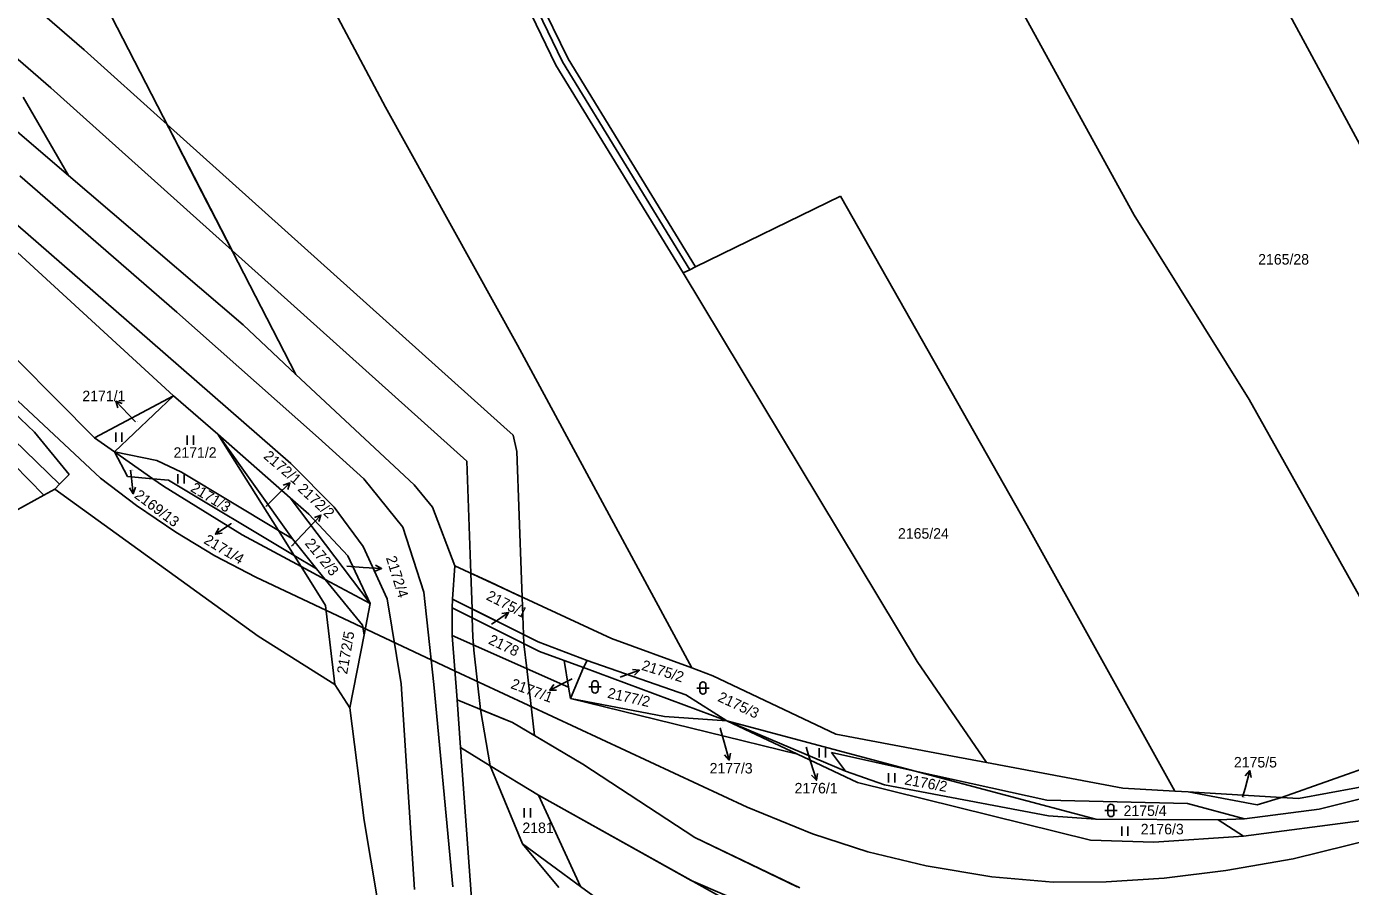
# Model space of a CAD drawing. Extents: x -785744 to -782822, y -1067550 to -1063910.
# Drawn here: x -784600.3 to -784386.3, y -1065176.5 to -1065037.5 of the extents above; entities that cross this region are included whole.
import ezdxf

# ---------------------------------------------------------------- set-up
doc = ezdxf.new("R2010")
doc.units = 0
for name, color, linetype in [('Hranice parcel', 7, 'Continuous'), ('Parcelní čísla', 7, 'Continuous'), ('Pop_ČP_popisy', 7, 'Continuous'), ('Poz_předměty', 7, 'Continuous'), ('Vnitřní kresba', 7, 'Continuous'), ('Věcná břemena k části', 7, 'Continuous'), ('Značky kultur', 7, 'Continuous')]:
    doc.layers.add(name, color=color, linetype=linetype)

msp = doc.modelspace()

# ---------------------------------------------------------------- linework, layer by layer
at = {"layer": 'Hranice parcel'}
for p, q in [((-784539.89, -1064986.55), (-784512.77, -1065042.73)), ((-784512.77, -1065042.73), (-784492.16, -1065076.37)), ((-784492.16, -1065076.37), (-784468.75, -1065064.93)), ((-784494.15, -1065077.35), (-784493.07, -1065076.82)), ((-784492.16, -1065076.37), (-784493.07, -1065076.82))]:
    msp.add_line(p, q, dxfattribs=at)
for points in [[(-784541.88, -1064987.52), (-784514.74, -1065043.73)], [(-784540.8, -1064986.99), (-784513.66, -1065043.21)], [(-784419.68, -1064992.12), (-784342.95, -1065133.93)], [(-784566.1, -1065005.58), (-784542.24, -1065050.56)], [(-784451.78, -1065012.48), (-784421.31, -1065068.01)], [(-784587.53, -1065033.99), (-784556.73, -1065093.75)], [(-784617.57, -1065041), (-784593.5, -1065061.6)], [(-784514.74, -1065043.73), (-784494.15, -1065077.35)], [(-784513.66, -1065043.21), (-784493.07, -1065076.82)], [(-784600.8, -1065048.94), (-784593.5, -1065061.6)], [(-784542.24, -1065050.56), (-784520.94, -1065089)], [(-784621.66, -1065055.78), (-784576.5, -1065097.19)], [(-784593.5, -1065061.6), (-784565.27, -1065085.75)], [(-784468.75, -1065064.93), (-784438.59, -1065118.18)], [(-784626.27, -1065066.7), (-784589.3, -1065104.01)], [(-784421.31, -1065068.01), (-784402.73, -1065097.8)], [(-784629.99, -1065077.48), (-784594.92, -1065111.49)], [(-784494.15, -1065077.35), (-784456.38, -1065140.15)], [(-784565.27, -1065085.75), (-784556.73, -1065093.75)], [(-784615.98, -1065086.94), (-784599, -1065103.07)], [(-784520.94, -1065089), (-784492.79, -1065141.2)], [(-784556.73, -1065093.75), (-784537.64, -1065111.6)], [(-784589.3, -1065104.01), (-784576.5, -1065097.19)], [(-784586.05, -1065106.28), (-784576.5, -1065097.19)], [(-784576.5, -1065097.19), (-784569.35, -1065103.39)], [(-784402.73, -1065097.8), (-784383.6, -1065131.92)], [(-784607.22, -1065103.37), (-784597.46, -1065113.27)], [(-784599, -1065103.07), (-784593.4, -1065109.93)], [(-784569.35, -1065103.39), (-784557.68, -1065113.69)], [(-784569.35, -1065103.39), (-784559.56, -1065118.97)], [(-784569.35, -1065103.39), (-784557.28, -1065120.34)], [(-784589.3, -1065104.01), (-784586.05, -1065106.28)], [(-784586.05, -1065106.28), (-784579.85, -1065110.62)], [(-784586.05, -1065106.28), (-784579.2, -1065107.69)], [(-784586.05, -1065106.28), (-784583.96, -1065110.27)], [(-784579.2, -1065107.69), (-784575.2, -1065109.54)], [(-784594.92, -1065111.49), (-784593.4, -1065109.93)], [(-784575.2, -1065109.54), (-784559.56, -1065118.97)], [(-784597.46, -1065113.27), (-784595.72, -1065112.31)], [(-784595.72, -1065112.31), (-784594.92, -1065111.49)], [(-784595.72, -1065112.31), (-784562.86, -1065136.09)], [(-784583.96, -1065110.27), (-784579.85, -1065110.62)], [(-784579.85, -1065110.62), (-784578.16, -1065111.8)], [(-784579.85, -1065110.62), (-784577.31, -1065110.83)], [(-784578.16, -1065111.8), (-784565.45, -1065119.69)], [(-784577.31, -1065110.83), (-784557.01, -1065123.02)], [(-784537.64, -1065111.6), (-784534.69, -1065115.21)], [(-784610.02, -1065120.18), (-784597.46, -1065113.27)], [(-784557.68, -1065113.69), (-784554.67, -1065116.35)], [(-784557.68, -1065113.69), (-784544.76, -1065130.8)], [(-784554.67, -1065116.35), (-784548.33, -1065123.07)], [(-784534.69, -1065115.21), (-784531.04, -1065124.71)], [(-784438.59, -1065118.18), (-784414.73, -1065161.11)], [(-784565.45, -1065119.69), (-784555.88, -1065124.82)], [(-784559.56, -1065118.97), (-784557.01, -1065123.02)], [(-784559.56, -1065118.97), (-784557.28, -1065120.34)], [(-784557.28, -1065120.34), (-784553.43, -1065125.17)], [(-784557.01, -1065123.02), (-784555.88, -1065124.82)], [(-784557.01, -1065123.02), (-784553.43, -1065125.17)], [(-784555.88, -1065124.82), (-784551.94, -1065131.11)], [(-784553.43, -1065125.17), (-784552.01, -1065126.9)], [(-784548.33, -1065123.07), (-784544.76, -1065130.8)], [(-784531.41, -1065130.09), (-784531.04, -1065124.71)], [(-784531.04, -1065124.71), (-784505.75, -1065136.43)], [(-784552.01, -1065126.9), (-784545.97, -1065134.28)], [(-784551.94, -1065131.11), (-784550.47, -1065143.88)], [(-784545.73, -1065135.83), (-784544.76, -1065130.8)], [(-784531.5, -1065131.51), (-784531.41, -1065130.09)], [(-784531.5, -1065131.51), (-784531.47, -1065135.94)], [(-784531.5, -1065131.51), (-784517.37, -1065138.54)], [(-784531.41, -1065130.09), (-784517.62, -1065136.96)], [(-784548.01, -1065147.63), (-784545.73, -1065135.83)], [(-784545.97, -1065134.28), (-784545.73, -1065135.83)], [(-784562.86, -1065136.09), (-784550.47, -1065143.88)], [(-784531.47, -1065135.94), (-784530.7, -1065146.35)], [(-784531.47, -1065135.94), (-784512.67, -1065144.33)], [(-784517.62, -1065136.96), (-784509.7, -1065140)], [(-784505.75, -1065136.43), (-784492.79, -1065141.2)], [(-784517.37, -1065138.54), (-784513.4, -1065140)], [(-784513.4, -1065140), (-784510.26, -1065141.16)], [(-784513.4, -1065140), (-784512.67, -1065144.33)], [(-784510.26, -1065141.16), (-784509.7, -1065140)], [(-784509.7, -1065140), (-784493.74, -1065145.57)], [(-784456.38, -1065140.15), (-784445.17, -1065156.49)], [(-784512.36, -1065146.16), (-784510.26, -1065141.16)], [(-784510.26, -1065141.16), (-784487.1, -1065149.73)], [(-784492.79, -1065141.2), (-784489.37, -1065142.46)], [(-784550.47, -1065143.88), (-784548.01, -1065147.63)], [(-784512.67, -1065144.33), (-784512.36, -1065146.16)], [(-784489.37, -1065142.46), (-784469.49, -1065151.89)], [(-784530.7, -1065146.35), (-784530.14, -1065154.09)], [(-784530.7, -1065146.35), (-784521.73, -1065150.02)], [(-784512.36, -1065146.16), (-784490.18, -1065151.59)], [(-784512.36, -1065146.16), (-784497.18, -1065149.05)], [(-784493.74, -1065145.57), (-784487.1, -1065149.73)], [(-784548.01, -1065147.63), (-784545.73, -1065165.86)], [(-784521.73, -1065150.02), (-784510.4, -1065156.75)], [(-784497.18, -1065149.05), (-784487.1, -1065149.73)], [(-784487.1, -1065149.73), (-784475.67, -1065155.14)], [(-784487.1, -1065149.73), (-784456.68, -1065157.87)], [(-784487.1, -1065149.73), (-784467.95, -1065157.91)], [(-784490.18, -1065151.59), (-784475.67, -1065155.14)], [(-784469.49, -1065151.89), (-784450.65, -1065155.46)], [(-784530.14, -1065154.09), (-784525.37, -1065157.01)], [(-784470.2, -1065154.86), (-784467.95, -1065157.91)], [(-784470.2, -1065154.86), (-784456.68, -1065157.87)], [(-784397.47, -1065162.14), (-784373.73, -1065153.73)], [(-784525.37, -1065157.01), (-784524.29, -1065159.63)], [(-784525.37, -1065157.01), (-784517.54, -1065161.79)], [(-784510.4, -1065156.75), (-784492.27, -1065168.61)], [(-784475.67, -1065155.14), (-784466.01, -1065159.72)], [(-784450.65, -1065155.46), (-784445.17, -1065156.49)], [(-784445.17, -1065156.49), (-784423.13, -1065160.62)], [(-784467.95, -1065157.91), (-784461.62, -1065160.11)], [(-784456.68, -1065157.87), (-784427.51, -1065165.67)], [(-784456.68, -1065157.87), (-784435.4, -1065162.6)], [(-784524.29, -1065159.63), (-784520.15, -1065169.65)], [(-784466.01, -1065159.72), (-784428.36, -1065169.07)], [(-784461.62, -1065160.11), (-784435.14, -1065165.11)], [(-784423.13, -1065160.62), (-784414.73, -1065161.11)], [(-784414.73, -1065161.11), (-784412.59, -1065161.24)], [(-784412.59, -1065161.24), (-784397.47, -1065162.14)], [(-784412.59, -1065161.24), (-784401.42, -1065163.33)], [(-784394.73, -1065162.3), (-784380.67, -1065159.75)], [(-784391.41, -1065164.06), (-784380.82, -1065161.38)], [(-784517.54, -1065161.79), (-784510.74, -1065176.52)], [(-784517.54, -1065161.79), (-784473.06, -1065186.61)], [(-784435.4, -1065162.6), (-784412.66, -1065163.11)], [(-784412.66, -1065163.11), (-784403.48, -1065165.61)], [(-784401.42, -1065163.33), (-784397.47, -1065162.14)], [(-784397.47, -1065162.14), (-784394.73, -1065162.3)], [(-784435.14, -1065165.11), (-784427.51, -1065165.67)], [(-784427.51, -1065165.67), (-784407.7, -1065165.74)], [(-784407.7, -1065165.74), (-784403.48, -1065165.61)], [(-784407.7, -1065165.74), (-784403.6, -1065168.42)], [(-784403.48, -1065165.61), (-784391.41, -1065164.06)], [(-784545.73, -1065165.86), (-784542.54, -1065184.81)], [(-784403.6, -1065168.42), (-784384.72, -1065165.94)], [(-784520.15, -1065169.65), (-784514.28, -1065176.7)], [(-784520.15, -1065169.65), (-784510.74, -1065176.52)], [(-784492.27, -1065168.61), (-784475.72, -1065176.6)], [(-784428.36, -1065169.07), (-784418.13, -1065169.38)], [(-784418.13, -1065169.38), (-784403.6, -1065168.42)], [(-784510.74, -1065176.52), (-784504.17, -1065181.33)]]:
    msp.add_lwpolyline(points, dxfattribs=at)
at = {"layer": 'Pop_ČP_popisy'}
for p, q in [((-784583.79, -1065100.25), (-784585.86, -1065098.08)), ((-784583.38, -1065110.06), (-784583.03, -1065113.04)), ((-784559.85, -1065113.4), (-784557.71, -1065111.3)), ((-784554.77, -1065118.65), (-784552.7, -1065116.48)), ((-784567.23, -1065117.93), (-784569.75, -1065119.55)), ((-784545.89, -1065124.94), (-784542.9, -1065125.13)), ((-784524.84, -1065133.94), (-784522.37, -1065132.24)), ((-784504.06, -1065142.59), (-784501.23, -1065141.59)), ((-784513.05, -1065143.43), (-784515.72, -1065144.79)), ((-784487.55, -1065153.2), (-784486.73, -1065156.09)), ((-784473.52, -1065156.49), (-784472.64, -1065159.36)), ((-784403.38, -1065160.71), (-784402.59, -1065157.81))]:
    msp.add_line(p, q, dxfattribs=at)
for points in [[(-784585.53, -1065099.15), (-784585.86, -1065098.08), (-784584.81, -1065098.46)], [(-784582.66, -1065101.43), (-784583.79, -1065100.25)], [(-784583.48, -1065109.24), (-784583.38, -1065110.06)], [(-784582.65, -1065111.99), (-784583.03, -1065113.04), (-784583.64, -1065112.1)], [(-784558.78, -1065111.64), (-784557.71, -1065111.3), (-784558.07, -1065112.35)], [(-784561.6, -1065115.13), (-784559.85, -1065113.4)], [(-784553.75, -1065116.86), (-784552.7, -1065116.48), (-784553.03, -1065117.54)], [(-784568.64, -1065119.43), (-784569.75, -1065119.55), (-784569.18, -1065118.59)], [(-784567.21, -1065117.92), (-784567.23, -1065117.93)], [(-784557.47, -1065121.5), (-784554.77, -1065118.65)], [(-784548.53, -1065124.77), (-784545.89, -1065124.94)], [(-784543.86, -1065124.57), (-784542.9, -1065125.13), (-784543.93, -1065125.57)], [(-784523.47, -1065132.4), (-784522.37, -1065132.24), (-784522.91, -1065133.22)], [(-784525.11, -1065134.12), (-784524.84, -1065133.94)], [(-784502.34, -1065141.45), (-784501.23, -1065141.59), (-784502.01, -1065142.39)], [(-784514.61, -1065144.78), (-784515.72, -1065144.79), (-784515.06, -1065143.89)], [(-784512.12, -1065142.96), (-784513.05, -1065143.43)], [(-784504.37, -1065142.7), (-784504.06, -1065142.59)], [(-784488.2, -1065150.92), (-784487.55, -1065153.2)], [(-784486.52, -1065154.99), (-784486.73, -1065156.09), (-784487.48, -1065155.26)], [(-784474.27, -1065154.03), (-784473.52, -1065156.49)], [(-784472.46, -1065158.26), (-784472.64, -1065159.36), (-784473.41, -1065158.55)], [(-784403.34, -1065158.65), (-784402.59, -1065157.81), (-784402.37, -1065158.91)], [(-784403.76, -1065162.12), (-784403.38, -1065160.71)]]:
    msp.add_lwpolyline(points, dxfattribs=at)
at = {"layer": 'Poz_předměty'}
for points in [[(-784694.26, -1065011.35), (-784588.33, -1065110.53)], [(-784588.33, -1065110.53), (-784582.48, -1065114.93)], [(-784582.48, -1065114.93), (-784576.16, -1065119.28)], [(-784576.16, -1065119.28), (-784569.82, -1065123.06)], [(-784569.82, -1065123.06), (-784563.2, -1065126.53)], [(-784530.98, -1065141.73), (-784563.2, -1065126.53)], [(-784483.8, -1065163.71), (-784530.98, -1065141.73)], [(-784473.25, -1065168.02), (-784483.8, -1065163.71)], [(-784464.35, -1065170.93), (-784473.25, -1065168.02)], [(-784382.32, -1065168.78), (-784395.62, -1065172.09)], [(-784454.88, -1065173.19), (-784464.35, -1065170.93)], [(-784395.62, -1065172.09), (-784406.49, -1065173.95)], [(-784444.28, -1065174.96), (-784454.88, -1065173.19)], [(-784406.49, -1065173.95), (-784416.46, -1065175.2)], [(-784434.38, -1065175.83), (-784444.28, -1065174.96)], [(-784425.84, -1065175.79), (-784434.38, -1065175.83)], [(-784416.46, -1065175.2), (-784425.84, -1065175.79)]]:
    msp.add_lwpolyline(points, dxfattribs=at)
at = {"layer": 'Vnitřní kresba'}
for points in [[(-784601.33, -1065061.67), (-784575.97, -1065083.69)], [(-784605.52, -1065066.37), (-784580.33, -1065088.26)], [(-784575.97, -1065083.69), (-784553.07, -1065103.99)], [(-784580.33, -1065088.26), (-784557.54, -1065108.16)], [(-784553.07, -1065103.99), (-784545.77, -1065110.64)], [(-784557.54, -1065108.16), (-784550.56, -1065115.21)], [(-784545.77, -1065110.64), (-784539.45, -1065118.44)], [(-784550.56, -1065115.21), (-784545.88, -1065121.58)], [(-784539.45, -1065118.44), (-784536.05, -1065128.98)], [(-784545.88, -1065121.58), (-784542.02, -1065130.02)], [(-784555.88, -1065124.82), (-784552.01, -1065126.9)], [(-784552.01, -1065126.9), (-784544.76, -1065130.8)], [(-784536.05, -1065128.98), (-784534.44, -1065143.88)], [(-784542.02, -1065130.02), (-784539.74, -1065143.76)], [(-784539.74, -1065143.76), (-784537.59, -1065177.01)], [(-784534.44, -1065143.88), (-784531.38, -1065176.57)], [(-784530.14, -1065154.09), (-784526.22, -1065208.06)]]:
    msp.add_lwpolyline(points, dxfattribs=at)
at = {"layer": 'Věcná břemena k části'}
for points in [[(-784590.98, -1065041.27), (-784600.12, -1065033.37), (-784610.8, -1065024.59)], [(-784610.8, -1065024.59), (-784609.16, -1065029.44), (-784604.47, -1065040.38), (-784596.36, -1065047.39)], [(-784577.56, -1065053.32), (-784590.98, -1065041.27)], [(-784596.36, -1065047.39), (-784567.05, -1065073.73), (-784577.56, -1065053.32)], [(-784523.13, -1065102.24), (-784577.56, -1065053.32)], [(-784577.56, -1065053.32), (-784573.76, -1065060.71)], [(-784573.76, -1065060.71), (-784571, -1065066.07)], [(-784571, -1065066.07), (-784567.05, -1065073.73)], [(-784567.05, -1065073.73), (-784529.13, -1065107.8)], [(-784521.66, -1065103.58), (-784523.13, -1065102.24)], [(-784521.03, -1065106.2), (-784521.66, -1065103.58)], [(-784529.13, -1065107.8), (-784528.47, -1065125.9)], [(-784520.28, -1065126.89), (-784521.03, -1065106.2)], [(-784520.19, -1065129.74), (-784528.47, -1065125.9)], [(-784528.47, -1065125.9), (-784528.28, -1065131.65)], [(-784528.47, -1065125.9), (-784525.43, -1065127.31)], [(-784525.43, -1065127.31), (-784523.25, -1065128.32)], [(-784520.19, -1065129.74), (-784520.28, -1065126.89)], [(-784523.25, -1065128.32), (-784520.19, -1065129.74)], [(-784519.99, -1065135.78), (-784520.19, -1065129.74)], [(-784528.28, -1065131.65), (-784519.99, -1065135.78)], [(-784519.99, -1065135.78), (-784528.28, -1065131.65)], [(-784528.28, -1065131.65), (-784528.24, -1065133.13)], [(-784528.24, -1065133.13), (-784528.14, -1065136.21)], [(-784519.9, -1065137.28), (-784519.99, -1065135.78)], [(-784528.14, -1065136.21), (-784528.05, -1065137.47)], [(-784528.05, -1065137.47), (-784527.99, -1065138.32)], [(-784519.44, -1065141.31), (-784519.9, -1065137.28)], [(-784527.99, -1065138.32), (-784526.89, -1065147.91)], [(-784518.2, -1065152.11), (-784519.44, -1065141.31)], [(-784523.72, -1065149.21), (-784526.89, -1065147.91)], [(-784526.89, -1065147.91), (-784525.37, -1065157.01)], [(-784526.89, -1065147.91), (-784523.72, -1065149.21)], [(-784521.73, -1065150.02), (-784523.72, -1065149.21)], [(-784523.72, -1065149.21), (-784521.73, -1065150.02)], [(-784518.2, -1065152.11), (-784521.73, -1065150.02)], [(-784521.73, -1065150.02), (-784518.2, -1065152.11)], [(-784510.4, -1065156.75), (-784518.2, -1065152.11)], [(-784525.37, -1065157.01), (-784517.54, -1065161.79)], [(-784492.27, -1065168.61), (-784510.4, -1065156.75)], [(-784517.54, -1065161.79), (-784492.86, -1065175.56)], [(-784475.31, -1065176.78), (-784492.27, -1065168.61)], [(-784492.86, -1065175.56), (-784477.47, -1065182.2)]]:
    msp.add_lwpolyline(points, dxfattribs=at)
at = {"layer": 'Značky kultur'}
for p, q in [((-784585.85, -1065104.63), (-784585.85, -1065103.13)), ((-784584.85, -1065104.63), (-784584.85, -1065103.13)), ((-784574.29, -1065105.12), (-784574.29, -1065103.62)), ((-784573.29, -1065105.12), (-784573.29, -1065103.62)), ((-784575.81, -1065111.39), (-784575.81, -1065109.89)), ((-784574.81, -1065111.39), (-784574.81, -1065109.89)), ((-784509.41, -1065144.27), (-784507.41, -1065144.27)), ((-784508.91, -1065144.77), (-784508.91, -1065143.77)), ((-784507.91, -1065143.77), (-784507.91, -1065144.77)), ((-784491.48, -1065144.95), (-784491.48, -1065143.95)), ((-784490.48, -1065143.95), (-784490.48, -1065144.95)), ((-784491.98, -1065144.45), (-784489.98, -1065144.45)), ((-784472.18, -1065155.7), (-784472.18, -1065154.2)), ((-784471.18, -1065155.7), (-784471.18, -1065154.2)), ((-784460.96, -1065159.72), (-784460.96, -1065158.22)), ((-784459.96, -1065159.72), (-784459.96, -1065158.22)), ((-784519.85, -1065165.36), (-784519.85, -1065163.86)), ((-784518.85, -1065165.36), (-784518.85, -1065163.86)), ((-784426.05, -1065164.24), (-784424.05, -1065164.24)), ((-784425.55, -1065164.74), (-784425.55, -1065163.74)), ((-784424.55, -1065163.74), (-784424.55, -1065164.74)), ((-784423.3, -1065168.33), (-784423.3, -1065166.83)), ((-784422.3, -1065168.33), (-784422.3, -1065166.83))]:
    msp.add_line(p, q, dxfattribs=at)
for centre, start, end in [((-784508.41, -1065143.77), 0, 180), ((-784490.98, -1065143.95), 0, 180), ((-784508.41, -1065144.77), 180, 0), ((-784490.98, -1065144.95), 180, 0), ((-784425.05, -1065163.74), 0, 180), ((-784425.05, -1065164.74), 180, 0)]:
    msp.add_arc(centre, 0.5, start, end, dxfattribs=at)

# ---------------------------------------------------------------- texts
at = {"layer": 'Parcelní čísla'}
for s, height, p in [('2165/28', 1.7, (-784401.25, -1065075.99)), ('2171/1', 0.1, (-784582.66, -1065101.43)), ('2171/2', 1.7, (-784576.51, -1065107.23)), ('2169/13', 0.1, (-784583.48, -1065109.24)), ('2172/1', 0.1, (-784561.6, -1065115.13)), ('2171/4', 0.1, (-784567.21, -1065117.92)), ('2165/24', 1.7, (-784459.45, -1065120.31)), ('2172/2', 0.1, (-784557.47, -1065121.5)), ('2172/4', 0.1, (-784548.53, -1065124.77)), ('2175/1', 0.1, (-784525.11, -1065134.12)), ('2177/1', 0.1, (-784512.12, -1065142.96)), ('2175/2', 0.1, (-784504.37, -1065142.7)), ('2177/3', 0.1, (-784488.2, -1065150.92)), ('2176/1', 0.1, (-784474.27, -1065154.03)), ('2175/4', 1.7, (-784423, -1065165.14)), ('2175/5', 0.1, (-784403.76, -1065162.12)), ('2181', 1.7, (-784520.14, -1065167.9)), ('2176/3', 1.7, (-784420.23, -1065168.11))]:
    msp.add_text(s, height=height, dxfattribs=at).set_placement(p)
for s, rotation, p in [('2171/3', 328.9209, (-784573.9, -1065112.55)), ('2172/3', 309.2894, (-784555.39, -1065121.11)), ('2172/5', 80.0973, (-784548.47, -1065142.29)), ('2178', 334.6059, (-784525.78, -1065137.23)), ('2177/2', 347.2585, (-784506.51, -1065146.01)), ('2175/3', 335.1174, (-784488.71, -1065146.51)), ('2176/2', 349.729, (-784458.5, -1065160.02))]:
    msp.add_text(s, height=1.7, rotation=rotation, dxfattribs=at).set_placement(p)
at = {"layer": 'Pop_ČP_popisy'}
for s, p in [('2171/1', (-784591.25, -1065098.08)), ('2177/3', (-784489.89, -1065158.27)), ('2175/5', (-784405.17, -1065157.3)), ('2176/1', (-784476.16, -1065161.49))]:
    msp.add_text(s, height=1.7, dxfattribs=at).set_placement(p)
for s, rotation, p in [('2172/1', 319.4584, (-784562.1, -1065107.18)), ('2172/2', 316.9844, (-784556.57, -1065112.42)), ('2169/13', 323.0307, (-784582.97, -1065113.58)), ('2171/4', 329.2171, (-784571.76, -1065120.96)), ('2172/4', 287.3005, (-784542.21, -1065123.39)), ('2175/1', 333.1769, (-784526.11, -1065130.09)), ('2175/2', 342.6139, (-784501.01, -1065141.48)), ('2177/1', 339.7082, (-784522.15, -1065144.44))]:
    msp.add_text(s, height=1.7, rotation=rotation, dxfattribs=at).set_placement(p)

doc.saveas('drawing.dxf')
